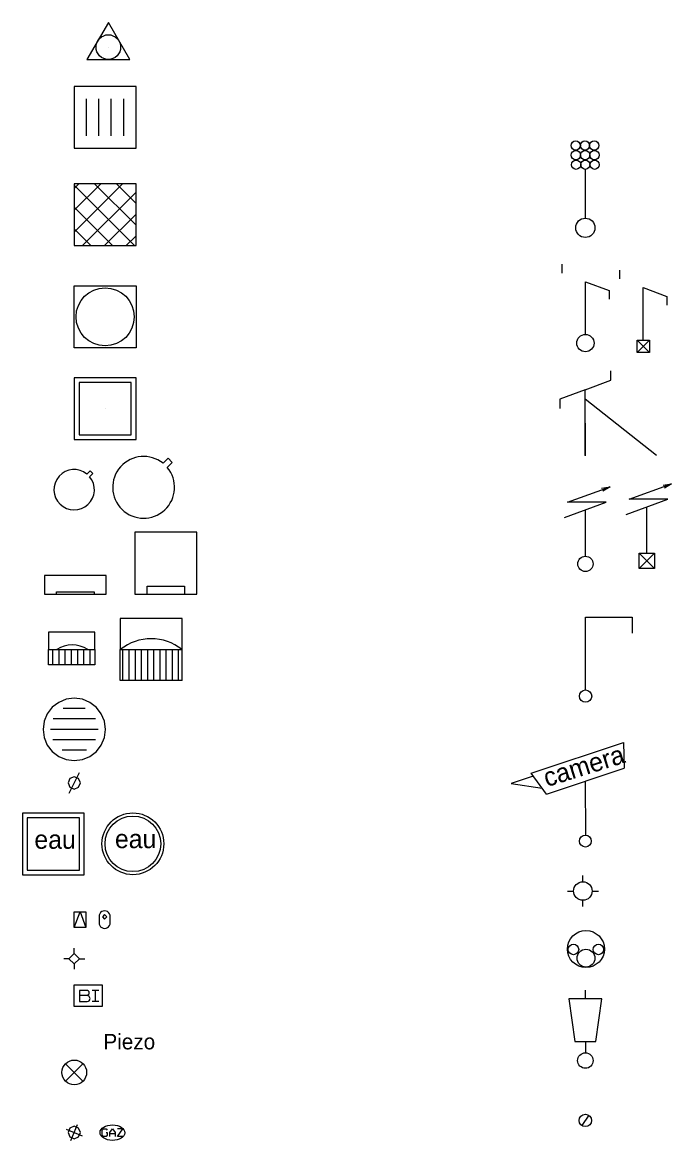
# Model space of a CAD drawing. Extents: x -1.5 to 18.2, y -66.6 to 3.3.
# Drawn here: x -0.84 to 9.66, y -14.77 to 3.32 of the extents above; entities that cross this region are included whole.
import ezdxf

# ---------------------------------------------------------------- set-up
doc = ezdxf.new("R2010")
doc.units = 0
for name, color, linetype in [('SOL_AFFLEUREMENT', 7, 'Continuous'), ('SOL_ALTIMETRIE', 7, 'Continuous'), ('SOL_AVALOIR', 7, 'Continuous'), ('SOL_AVALOIR_GRILLE', 7, 'Continuous'), ('SOL_BOUCHE_A_CLEF', 7, 'Continuous'), ('SOL_BOUCHES_ARROSAGE', 7, 'Continuous'), ('SOL_CANDELABRE', 7, 'Continuous'), ('SOL_EAU_CHAMBRES', 7, 'Continuous'), ('SOL_ELEC_POTEAU', 7, 'Continuous'), ('SOL_GRILLE', 7, 'Continuous'), ('SOL_MOBILIER_DIVERS', 7, 'Continuous'), ('SOL_PIEZOMETRE', 7, 'Continuous'), ('SOL_PLAQUE_GAZ', 7, 'Continuous'), ('SOL_POTEAU', 7, 'Continuous'), ('SOL_POTEAU_INCENDIE', 7, 'Continuous'), ('SOL_TELECOM_POTEAU', 7, 'Continuous'), ('SOL_TRAM_POTEAU_SIGNALISATION', 7, 'Continuous'), ('SOL_VENTILATION_GRILLE', 7, 'Continuous')]:
    doc.layers.add(name, color=color, linetype=linetype)

# ---------------------------------------------------------------- blocks, each defined once
blk = doc.blocks.new('GRILLE_RECTANGULAIRE')
for points in [[(0, 0), (1, 0), (1, 1), (0, 1), (0, 0)], [(0.2, 0.2), (0.2, 0.8)], [(0.4, 0.2), (0.4, 0.8)], [(0.6, 0.2), (0.6, 0.8)], [(0.8, 0.2), (0.8, 0.8)]]:
    blk.add_lwpolyline(points)
blk = doc.blocks.new('GRILLE_AERATION')
for p, q in [((0, 0.218), (0.782, 1)), ((0, 0.571), (0.429, 1)), ((0, 0.925), (0.075, 1)), ((0.975, 0), (0, 0.975)), ((1, 0.329), (0.329, 1)), ((1, 0.682), (0.682, 1)), ((0.136, 0), (1, 0.864)), ((0.621, 0), (0, 0.621)), ((0.49, 0), (1, 0.51)), ((0.268, 0), (0, 0.268)), ((0.843, 0), (1, 0.157))]:
    blk.add_line(p, q)
blk.add_lwpolyline([(0, 0), (1, 0), (1, 1), (0, 1), (0, 0)])
blk = doc.blocks.new('PLAQUE_CARREE')
blk.add_lwpolyline([(0, 1), (1, 1), (1, 0), (0, 0)], close=True)
blk.add_circle((0.5, 0.5), 0.47)
blk = doc.blocks.new('PLAQUE_RECTANGULAIRE')
blk.add_line((0.5, 0.5), (0.5, 0.5))
for points in [[(0, 0), (1, 0), (1, 1), (0, 1), (0, 0)], [(0.079, 0.079), (0.921, 0.079), (0.921, 0.921), (0.079, 0.921), (0.079, 0.079)]]:
    blk.add_lwpolyline(points)
blk = doc.blocks.new('PLAQUE_RONDE')
blk.add_lwpolyline([(0.205, 0.254), (0.259, 0.308), (0.303, 0.264), (0.25, 0.211)])
blk.add_arc((0, 0), 0.327, 51.0799, 40.1626)
blk = doc.blocks.new('AVALOIR')
for points in [[(0, 0), (1, 0), (1, 0.3), (0, 0.3), (0, 0)], [(0.197, 0), (0.197, 0.039), (0.803, 0.039), (0.803, 0)]]:
    blk.add_lwpolyline(points)
blk = doc.blocks.new('AVALOIR_GRILLE')
for p, q in [((0, -0.25), (0, 0)), ((0, 0), (0.75, 0)), ((0.072, -0.25), (0.072, 0)), ((0.172, -0.25), (0.172, 0)), ((0.272, -0.25), (0.272, 0)), ((0.372, -0.25), (0.372, 0)), ((0.472, -0.25), (0.472, 0)), ((0.572, -0.25), (0.572, 0)), ((0.672, -0.25), (0.672, 0)), ((0.75, 0), (0.75, -0.25)), ((0.75, -0.25), (0, -0.25))]:
    blk.add_line(p, q)
blk.add_lwpolyline([(0, 0), (0.75, 0), (0.75, 0.28), (0, 0.28)], close=True)
blk.add_lwpolyline([(0.136, 0), (0.635, 0)])
blk.add_arc((0.385, -0.391), 0.464, 57.4445, 122.5555)
blk = doc.blocks.new('GRILLE_RONDE')
for points in [[(0.362, 0.354), (0.255, 0.438), (0.132, 0.489), (0.001, 0.505), (-0.13, 0.489), (-0.249, 0.438), (-0.356, 0.358), (-0.436, 0.251), (-0.487, 0.132), (-0.503, 0.001), (-0.487, -0.13), (-0.436, -0.253), (-0.356, -0.356), (-0.249, -0.436), (-0.13, -0.487), (0.001, -0.503), (0.132, -0.487), (0.255, -0.436), (0.358, -0.356), (0.438, -0.253), (0.489, -0.13), (0.505, 0.001), (0.489, 0.132), (0.438, 0.251), (0.362, 0.354)], [(-0.178, 0.342), (0.176, 0.342)], [(-0.384, 0.005), (0.386, 0.005)], [(-0.34, 0.176), (0.342, 0.176)], [(-0.344, -0.162), (0.346, -0.162)], [(-0.193, -0.329), (0.199, -0.329)]]:
    blk.add_lwpolyline(points)
blk = doc.blocks.new('BOUCHE_CLEF_EAU')
for points in [[(0.101, 0.001), (0.071, 0.071), (0.001, 0.101), (-0.069, 0.071), (-0.099, 0.001), (-0.069, -0.069), (0.001, -0.099), (0.071, -0.069), (0.101, 0.001)], [(-0.083, -0.166), (0.084, 0.167)]]:
    blk.add_lwpolyline(points)
blk = doc.blocks.new("BOUCHE_D'ARROSAGE")
for points in [[(0, 0.25), (0.19, 0.25), (0.19, 0), (0, 0), (0, 0.25)], [(0, 0), (0.095, 0.25), (0.19, 0)]]:
    blk.add_lwpolyline(points)
blk = doc.blocks.new('ARROSEUR')
for points in [[(-0.0844, 0), (0.0002, 0.0852), (0.0854, 0), (0.0002, -0.0846), (-0.0844, 0), (-0.169, 0)], [(0.0002, 0.0852), (0.0002, 0.1698)], [(0.0854, 0), (0.17, 0)], [(0.0002, -0.0846), (0.0002, -0.1692)]]:
    blk.add_lwpolyline(points)
blk = doc.blocks.new('PLAQUE_INCENDIE')
for points in [[(0, 0), (0, 0.35), (0.45, 0.35), (0.45, 0), (0, 0)], [(0.207, 0.178), (0.223, 0.186), (0.232, 0.194), (0.241, 0.207), (0.243, 0.216), (0.243, 0.223), (0.241, 0.236), (0.232, 0.247), (0.214, 0.256), (0.195, 0.259), (0.085, 0.259), (0.085, 0.081), (0.207, 0.081), (0.229, 0.087), (0.243, 0.094), (0.252, 0.106), (0.255, 0.117), (0.257, 0.127), (0.255, 0.139), (0.25, 0.152), (0.243, 0.16), (0.227, 0.171), (0.207, 0.178), (0.085, 0.178)], [(0.399, 0.259), (0.292, 0.259)], [(0.345, 0.081), (0.345, 0.259)], [(0.399, 0.081), (0.292, 0.081)]]:
    blk.add_lwpolyline(points)
blk = doc.blocks.new('PIEZOMETRE')
for points in [[(-0.141, -0.141), (0.142, 0.142)], [(-0.141, 0.142), (0.142, -0.141)]]:
    blk.add_lwpolyline(points)
blk.add_circle((0.001, 0.001), 0.2)
blk.add_text('Piezo', height=0.25).set_placement((0.473, 0.374))
blk = doc.blocks.new('BOUCHE_CLEF_GAZ')
for points in [[(-0.132, 0.053), (0.13, -0.055)], [(0.1, 0), (0.07, 0.07), (0, 0.1), (-0.07, 0.07), (-0.1, 0), (-0.07, -0.07), (0, -0.1), (0.07, -0.07), (0.1, 0)], [(-0.054, -0.132), (0.053, 0.131)]]:
    blk.add_lwpolyline(points)
blk = doc.blocks.new('CANDELABRE_STADE')
blk.add_line((0, 0.15), (0, 0.941))
for centre, radius in [((-0.156, 1.327), 0.075), ((-0.006, 1.327), 0.075), ((0.144, 1.327), 0.075), ((-0.153, 1.172), 0.075), ((-0.15, 1.016), 0.075), ((-0.003, 1.172), 0.075), ((0, 1.016), 0.075), ((0.147, 1.172), 0.075), ((0.15, 1.016), 0.075), ((0, -0.005), 0.156)]:
    blk.add_circle(centre, radius)
blk = doc.blocks.new('POTEAU_TELECOM')
blk.add_line((0.001, 0.142), (0.001, 0.992))
for points in [[(-0.382, 1.276), (-0.382, 1.134)], [(0.001, 0.992), (0.384, 0.85)], [(0.384, 0.85), (0.384, 0.709)]]:
    blk.add_lwpolyline(points)
blk.add_circle((0.001, 0), 0.14)
blk = doc.blocks.new('POTEAU_TELECOM_2_ANCRAGES')
for p, q in [((0.41, 1.22), (0.41, 1.373)), ((-0.001, 1.067), (-0.412, 0.914)), ((-0.412, 0.914), (-0.411, 0.762)), ((1.149, 0.002), (-0.001, 0.913)), ((-0.001, 0.003), (-0.001, 0.853))]:
    blk.add_line(p, q)
blk.add_lwpolyline([(0.001, 0), (-0.001, 1.067), (0.41, 1.22)])
blk = doc.blocks.new('POTEAU_ELECTRIQUE')
blk.add_line((0, 0.124), (0, 0.875))
for points in [[(-0.337, 0.75), (0.338, 1), (-0.287, 1), (0.4, 1.25)], [(0.263, 1.225), (0.4, 1.25), (0.283, 1.18)]]:
    blk.add_lwpolyline(points)
blk.add_circle((0.001, 0.001), 0.124)
blk = doc.blocks.new('CATENAIRE')
blk.add_lwpolyline([(0.001, 0.098), (0.001, 1.273), (0.756, 1.273), (0.756, 1.015)])
blk.add_circle((0.003, -0.002), 0.1)
blk = doc.blocks.new('CAMERA')
for p, q in [((-0.878, 1.101), (0.615, 1.597)), ((-0.878, 1.101), (0.615, 1.597)), ((-0.627, 0.761), (0.627, 1.178)), ((-0.627, 0.761), (0.627, 1.178)), ((-0.001, 0.969), (0, 0.096)), ((-0.001, 0.969), (0, 0.096))]:
    blk.add_line(p, q)
for points in [[(0.615, 1.597), (0.627, 1.178)], [(0.615, 1.597), (0.627, 1.178)], [(-0.627, 0.761), (-0.878, 1.101)], [(-0.627, 0.761), (-0.878, 1.101)], [(-0.842, 1.053), (-1.202, 0.934), (-0.697, 0.855)], [(-0.842, 1.053), (-1.202, 0.934), (-0.697, 0.855)]]:
    blk.add_lwpolyline(points)
blk.add_circle((0, 0), 0.0964)
blk.add_circle((0, 0), 0.0964)
blk.add_text('camera', height=0.3017, rotation=17.4006).set_placement((-0.622, 0.872))
blk = doc.blocks.new('POTEAU_INCENDIE')
for centre, radius in [((0.001, 0), 0.299), ((-0.201, -0.007), 0.085), ((0.202, -0.007), 0.085), ((0.001, -0.148), 0.144)]:
    blk.add_circle(centre, radius)
blk = doc.blocks.new('POUBELLE')
for p, q in [((0, 1), (0, 1.137)), ((0, 0.307), (0, 0.125))]:
    blk.add_line(p, q)
blk.add_lwpolyline([(-0.172, 0.307), (0.172, 0.307), (0.268, 1), (-0.268, 1)], close=True)
blk.add_circle((0, 0), 0.125)
blk = doc.blocks.new('POTEAU_ROND')
blk.add_line((0.056, 0.083), (-0.056, -0.083))
blk.add_circle((0, 0), 0.1)
blk = doc.blocks.new('POTEAU_ELECTRIQUE_BETON')
for p, q in [((0, 0.124), (0, 0.875)), ((-0.123, 0.124), (0.124, -0.123)), ((0.124, 0.124), (-0.123, -0.123))]:
    blk.add_line(p, q)
for points in [[(-0.337, 0.75), (0.338, 1), (-0.287, 1), (0.4, 1.25)], [(0.263, 1.225), (0.4, 1.25), (0.283, 1.18)]]:
    blk.add_lwpolyline(points)
blk.add_lwpolyline([(-0.123, 0.124), (0.124, 0.124), (0.124, -0.123), (-0.123, -0.123)], close=True)
blk = doc.blocks.new('PLAQUE_RONDE_1M_DIAMETRE')
blk.add_lwpolyline([(0.314, 0.389), (0.395, 0.47), (0.463, 0.403), (0.382, 0.322)])
blk.add_arc((0, 0), 0.5, 51.0799, 40.1626)
blk = doc.blocks.new('POTEAU_TELECOM_BETON')
for p, q in [((0.001, 0.142), (0.001, 0.992)), ((-0.099, -0.058), (0.101, 0.142)), ((-0.099, 0.142), (0.101, -0.058))]:
    blk.add_line(p, q)
for points in [[(-0.382, 1.276), (-0.382, 1.134)], [(0.001, 0.992), (0.384, 0.85)], [(0.384, 0.85), (0.384, 0.709)]]:
    blk.add_lwpolyline(points)
blk.add_lwpolyline([(-0.099, 0.142), (0.101, 0.142), (0.101, -0.058), (-0.099, -0.058)], close=True)
blk = doc.blocks.new('PLAQUE_EAU_POTABLE')
blk.add_line((0.5, 0.5), (0.5, 0.5))
for points in [[(0, 0), (1, 0), (1, 1), (0, 1), (0, 0)], [(0.079, 0.079), (0.921, 0.079), (0.921, 0.921), (0.079, 0.921), (0.079, 0.079)]]:
    blk.add_lwpolyline(points)
blk.add_text('eau', height=0.3).set_placement((0.194, 0.423))
blk = doc.blocks.new('PLAQUE_EAU_POTABLE_RONDE')
blk.add_line((0, 0), (0, 0))
for radius in [0.5, 0.45]:
    blk.add_circle((0, 0), radius)
blk.add_text('eau', height=0.3).set_placement((-0.29, -0.07))
blk = doc.blocks.new('BORNE_OGE')
for p, q in [((0, 0.15), (0, 0.25)), ((-0.25, 0), (-0.15, 0)), ((0, -0.25), (0, -0.15)), ((0.15, 0), (0.25, 0))]:
    blk.add_line(p, q)
blk.add_circle((0, 0), 0.15)
blk = doc.blocks.new('POINT_DISPLAY')
blk.add_line((0, 0), (0, 0))
blk = doc.blocks.new('STATION_TOPO')
blk.add_lwpolyline([(0, 0.4), (-0.346, -0.2), (0.346, -0.2)], close=True)
blk.add_ellipse((0, 0), major_axis=(0.141, 0.141), ratio=0.999928)
at = {"xscale": 0.1, "yscale": 0.10000000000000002}
blk.add_blockref('POINT_DISPLAY', (0, 0), dxfattribs=at)
blk = doc.blocks.new('AVALOIR_GRILLE_DIM_1X1')
for p, q in [((1, 0.5), (0, 0.5)), ((0, 0.5), (0, 0)), ((1, 0), (1, 0.5)), ((0, 0.22), (0, 0.22)), ((0, 0), (1, 0)), ((0, -0.5), (0, 0)), ((0.044, -0.5), (0.044, 0)), ((0.144, -0.5), (0.144, 0)), ((0.244, -0.5), (0.244, 0)), ((0.344, -0.5), (0.344, 0)), ((0.444, -0.5), (0.444, 0)), ((0.544, -0.5), (0.544, 0)), ((0.644, -0.5), (0.644, 0)), ((0.744, -0.5), (0.744, 0)), ((0.844, -0.5), (0.844, 0)), ((0.944, -0.5), (0.944, 0)), ((1, -0.5), (1, 0)), ((1, -0.5), (0, -0.5)), ((0, -0.5), (0, -0.5))]:
    blk.add_line(p, q)
blk.add_lwpolyline([(0, 0), (1, 0)])
blk.add_arc((0.5, -0.628), 0.802, 51.4529, 128.5471)
blk = doc.blocks.new('AVALOIR_DIM_1X1')
for points in [[(0, 0), (1, 0), (1, 1), (0, 1), (0, 0)], [(0.197, 0), (0.197, 0.13), (0.803, 0.13), (0.803, 0)]]:
    blk.add_lwpolyline(points)
blk = doc.blocks.new('PLAQUE_GAZ_OVALE')
for points in [[(-0.103, 0.001), (-0.083, 0.001), (-0.083, -0.041), (-0.103, -0.063), (-0.145, -0.063), (-0.167, -0.041), (-0.167, 0.042), (-0.145, 0.063), (-0.103, 0.063), (-0.083, 0.042)], [(-0.042, -0.063), (-0.042, 0.001), (0.001, 0.063), (0.042, 0.001), (0.042, -0.063)], [(0.168, -0.063), (0.083, -0.063), (0.168, 0.063), (0.083, 0.063)], [(0.042, -0.02), (-0.042, -0.02)]]:
    blk.add_lwpolyline(points)
blk.add_ellipse((0, 0), major_axis=(-0.2, 0.003), ratio=0.625)
blk = doc.blocks.new("BOUCHE_D'ARROSAGE_OVALE")
for p, q in [((-0.09, 0.05), (-0.09, -0.05)), ((0, 0.08), (-0.035, 0.045)), ((-0.035, 0.045), (0, 0.009)), ((0.035, 0.045), (0, 0.08)), ((0, 0.009), (0.035, 0.045)), ((0.09, -0.05), (0.09, 0.05))]:
    blk.add_line(p, q)
for centre, start, end in [((0, 0.052), 358.5854, 181.4112), ((0, -0.052), 178.5856, 1.4144)]:
    blk.add_arc(centre, 0.09, start, end)

msp = doc.modelspace()

# ---------------------------------------------------------------- block references
at = {"layer": 'SOL_AFFLEUREMENT'}
for name, p in [('PLAQUE_CARREE', (0, -1.945)), ('PLAQUE_RECTANGULAIRE', (0, -3.431)), ('PLAQUE_RONDE_1M_DIAMETRE', (1.123, -4.204)), ('PLAQUE_RONDE', (0, -4.243)), ('ARROSEUR', (0, -11.832)), ('PLAQUE_INCENDIE', (0, -12.604))]:
    msp.add_blockref(name, p, dxfattribs=at)
at = {"layer": 'SOL_ALTIMETRIE'}
msp.add_blockref('STATION_TOPO', (0.552, 2.919), dxfattribs=at)
at = {"layer": 'SOL_AVALOIR'}
for name, p in [('AVALOIR_DIM_1X1', (0.982, -5.932)), ('AVALOIR', (-0.481, -5.932))]:
    msp.add_blockref(name, p, dxfattribs=at)
at = {"layer": 'SOL_AVALOIR_GRILLE'}
for name, p in [('AVALOIR_GRILLE_DIM_1X1', (0.745, -6.828)), ('AVALOIR_GRILLE', (-0.416, -6.828))]:
    msp.add_blockref(name, p, dxfattribs=at)
at = {"layer": 'SOL_BOUCHE_A_CLEF'}
msp.add_blockref('BOUCHE_CLEF_EAU', (0, -8.987), dxfattribs=at)
at = {"layer": 'SOL_BOUCHES_ARROSAGE'}
for name, p in [("BOUCHE_D'ARROSAGE", (0, -11.325)), ("BOUCHE_D'ARROSAGE_OVALE", (0.492, -11.198))]:
    msp.add_blockref(name, p, dxfattribs=at)
at = {"layer": 'SOL_CANDELABRE'}
msp.add_blockref('CANDELABRE_STADE', (8.267, 0), dxfattribs=at)
at = {"layer": 'SOL_EAU_CHAMBRES'}
for name, p in [('PLAQUE_EAU_POTABLE', (-0.838, -10.475)), ('PLAQUE_EAU_POTABLE_RONDE', (0.949, -9.972))]:
    msp.add_blockref(name, p, dxfattribs=at)
at = {"layer": 'SOL_ELEC_POTEAU'}
for name, p in [('POTEAU_ELECTRIQUE_BETON', (9.262, -5.396)), ('POTEAU_ELECTRIQUE', (8.267, -5.444))]:
    msp.add_blockref(name, p, dxfattribs=at)
at = {"layer": 'SOL_GRILLE'}
for name, p in [('GRILLE_RECTANGULAIRE', (0, 1.283)), ('GRILLE_RONDE', (0, -8.121))]:
    msp.add_blockref(name, p, dxfattribs=at)
at = {"layer": 'SOL_MOBILIER_DIVERS'}
for name, p in [('CAMERA', (8.267, -9.928)), ('BORNE_OGE', (8.227, -10.736)), ('POUBELLE', (8.267, -13.479))]:
    msp.add_blockref(name, p, dxfattribs=at)
at = {"layer": 'SOL_PIEZOMETRE'}
msp.add_blockref('PIEZOMETRE', (0, -13.672), dxfattribs=at)
at = {"layer": 'SOL_PLAQUE_GAZ'}
for name, p in [('BOUCHE_CLEF_GAZ', (0, -14.643)), ('PLAQUE_GAZ_OVALE', (0.618, -14.645))]:
    msp.add_blockref(name, p, dxfattribs=at)
at = {"layer": 'SOL_POTEAU'}
msp.add_blockref('POTEAU_ROND', (8.267, -14.448), dxfattribs=at)
at = {"layer": 'SOL_POTEAU_INCENDIE'}
msp.add_blockref('POTEAU_INCENDIE', (8.276, -11.674), dxfattribs=at)
at = {"layer": 'SOL_TELECOM_POTEAU'}
for name, p in [('POTEAU_TELECOM', (8.267, -1.871)), ('POTEAU_TELECOM_BETON', (9.203, -1.964)), ('POTEAU_TELECOM_2_ANCRAGES', (8.267, -3.692))]:
    msp.add_blockref(name, p, dxfattribs=at)
at = {"layer": 'SOL_TRAM_POTEAU_SIGNALISATION'}
msp.add_blockref('CATENAIRE', (8.267, -7.58), dxfattribs=at)
at = {"layer": 'SOL_VENTILATION_GRILLE'}
msp.add_blockref('GRILLE_AERATION', (0, -0.292), dxfattribs=at)

doc.saveas('drawing.dxf')
